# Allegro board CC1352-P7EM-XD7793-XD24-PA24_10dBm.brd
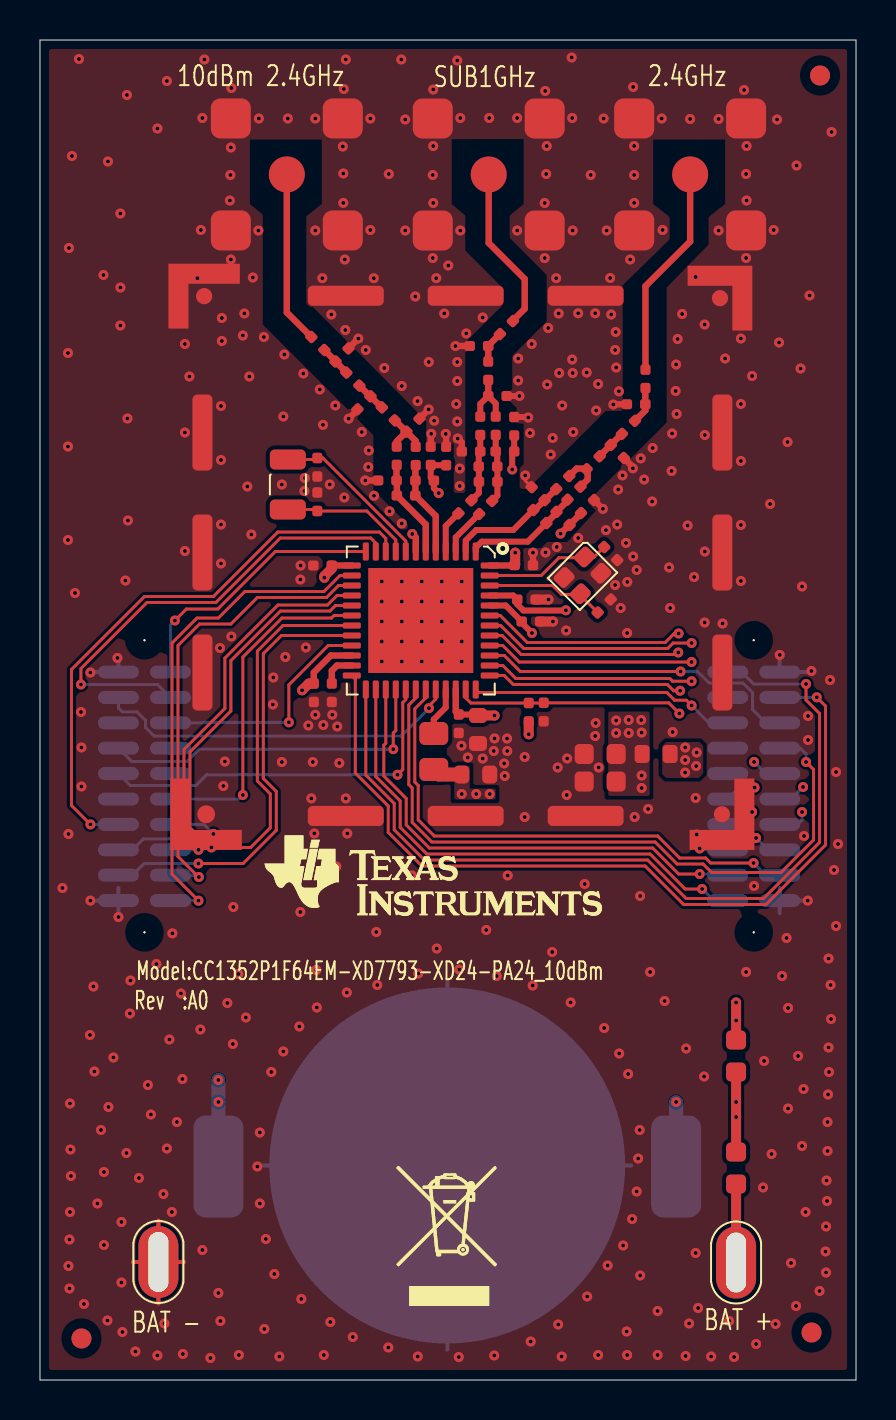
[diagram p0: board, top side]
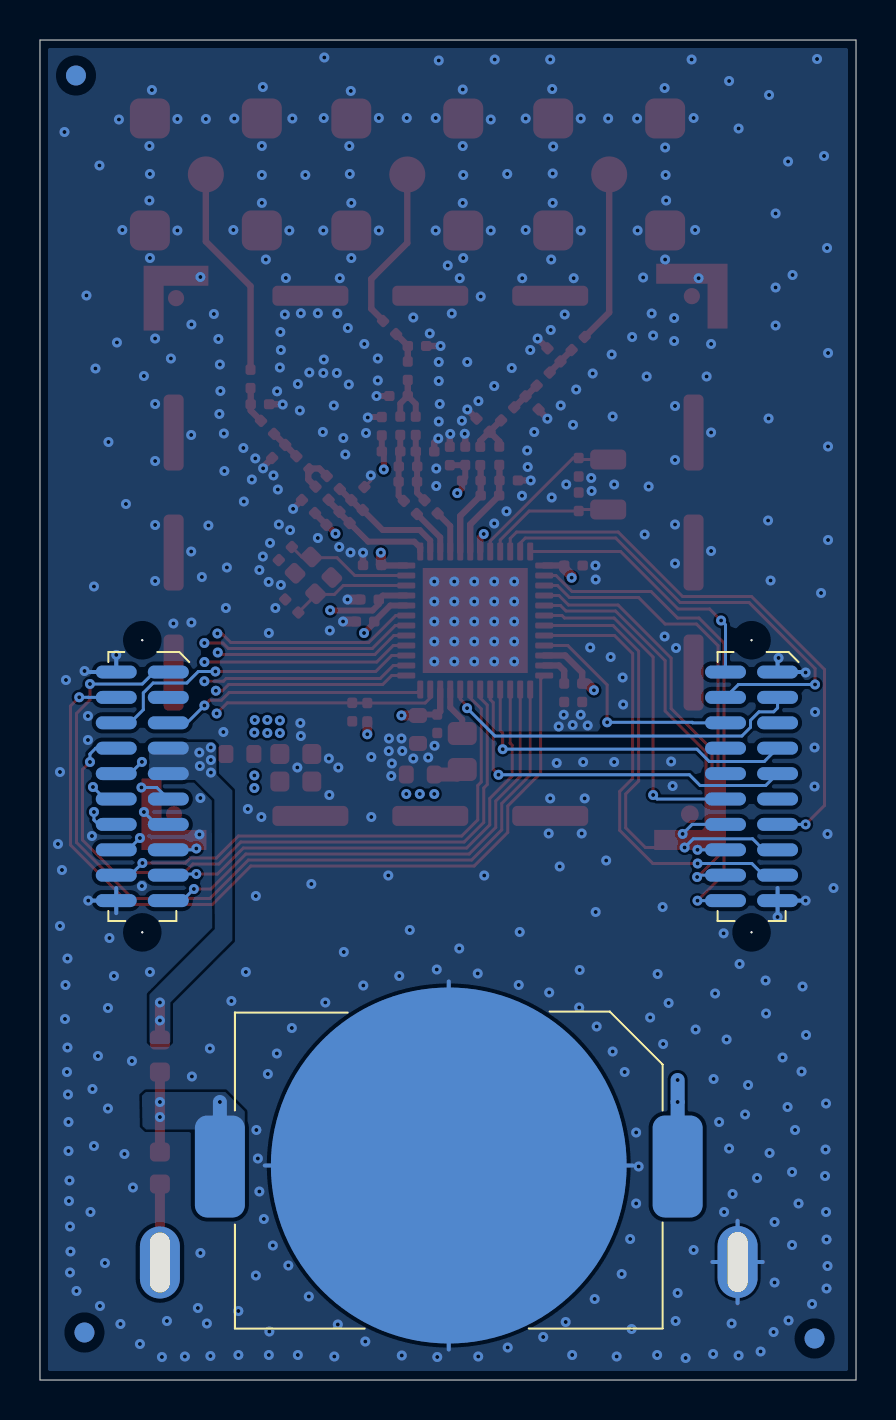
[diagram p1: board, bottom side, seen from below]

Outline 40.83 x 67 mm; copper layers: TOP, L2, L3, BOTTOM. Coordinates in mm from the lower left corner of the outline.
Outline path: 0,67 0,0 40.83,0 40.83,67 0,67

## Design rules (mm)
constraint set DEFAULT: min track width 0.15

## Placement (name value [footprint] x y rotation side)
BAT+1  BAT+  [PAD_S2000OBL3600_1000M3000]  34.83 5.88 0 top
BAT-1  BAT-  [PAD_S2000OBL3600_1000M3000]  5.92 5.9 0 top
BT1  BAT-HLD-001  [BAT_BATHLD001N]  8.92 10.68 0 bottom
C1  22uF  [CAPC1608X100A2N#2]  28.83 29.93 180 top
C2  22uF  [CAPC1608X100A2N#2]  28.83 31.3 180 top
C11  12pF  [CAPC1005X60B2N]  27.06 43.35 45 top
C12  1.1pF  [CAPC1005X60B2N]  26.39 44.01 45 top
C13  1pF  [CAPC1005X60B2N]  28.56 46.75 315 top
C14  1pF  [CAPC1005X60B2N]  30.28 48.79 180 top
C15  12pF  [CAPC1005X60B2N]  30.29 49.59 90 top
C21  1.1pF  [CAPC1005X60B2N]  25.25 43.99 135 top
C31  1.2pF  [CAPC1005X60B2N]  22.88 44.92 180 top
C32  100pF  [CAPC1005X60B2N]  23.73 47.23 90 top
C33  3pF  [CAPC1005X60B2N]  22.8 47.25 90 top
C34  2.7pF  [CAPC1005X60B2N]  22.42 49.2 0 top
C35  5.6pF  [CAPC1005X60B2N]  21.5 51.7 0 top
C36  100pF  [CAPC1005X60B2N]  23.66 52.95 225 top
C41  3pF  [CAPC1005X60B2N]  21.1 46.43 0 top
C51  12pF  [CAPC1005X60B2N]  19.55 46.67 270 top
C52  10nF  [CAPC1005X60B2N]  20.32 45.74 90 top
C53  1.2pF  [CAPC1005X60B2N]  18.8 45.74 90 top
C54  1.2pF  [CAPC1005X60B2N]  18.33 47.42 45 top
C55  1.4pF  [CAPC1005X60B2N]  16.53 49.18 225 top
C56  1.6pF  [CAPC1005X60B2N]  14.78 50.93 45 top
C57  6.8pF  [CAPC1005X60B2N]  14.23 51.5 135 top
C61  1.2pF  [CAPC1005X60B2N]  16.91 44.98 0 top
C81  12pF  [CAPC1005X60B2N]  13.88 46.1 270 top
C91  12pF  [CAPC1005X60B2N]  13.88 43.45 90 top
C131  0.1uF  [CAPC1005X60B2N]  14.6 40.73 180 top
C221  0.1uF  [CAPC1005X60B2N]  13.7 34.83 270 top
C231  1uF  [CAPC1005X60B2N]  14.6 34.83 270 top
C331  22uF  [CAPC1608X100A2N]  21.1 30.28 0 top
C341  22uF  [CAPC1608X100A2N]  21.91 33.23 270 top
C342  0.1uF  [CAPC1005X60B2N]  20.95 33.28 270 top
C351  0.1uF  [CAPC1005X60B2N]  25.2 33.86 270 top
C441  0.1uF  [CAPC1005X60B2N]  24.1 37.93 0 top
C451  0.1uF  [CAPC1005X60B2N]  23.87 39.03 0 top
C461  7.5pF  [CAPC1005X60B2N]  27.9 38.38 45 top
C471  7.5pF  [CAPC1005X60B2N]  28.23 41.65 315 top
C481  0.1uF  [CAPC1005X60B2N]  23.74 40.74 0 top
FIDU1  FIDU_1MM  [FID100X115B]  2.08 2.08 0 top
FIDU2  FIDU_1MM  [FID100X115B]  38.6 2.38 0 top
FIDU3  FIDU_1MM  [FID100X115B]  39.02 65.22 0 top
FIDU4  FIDU_1MM  [FID100X115B]  2.08 2.08 180 bottom
FIDU5  FIDU_1MM  [FID100X115B]  38.6 2.38 180 bottom
FIDU6  FIDU_1MM  [FID100X115B]  39.02 65.22 180 bottom
FL1  BLM18HE152SN1  [FIL_BLM18HE152SN1DN]  30.12 31.3 0 top
J1  SMA-10V21-TGG  [HUSTSAN_SMA10V21TGGAN]  22.45 60.28 0 top
J2  SMA-10V21-TGG  [HUSTSAN_SMA10V21TGGAN]  32.53 60.28 0 top
J3  SMA-10V21-TGG  [HUSTSAN_SMA10V21TGGAN]  12.35 60.28 0 top
L11  15nH  [INDC1005X60D2N]  25.33 42.85 135 top
L12  2.4nH  [INDC1005X60D2N]  26.49 42.76 135 top
L13  1.5nH  [INDC1005X60D2N]  27.35 45.54 45 top
L14  2nH  [INDC1005X60D2N]  29.11 47.31 45 top
L21  2.4nH  [INDC1005X60D2N]  25.83 44.55 45 top
L31  3.9nH  [INDC1005X60D2N]  21.97 43.3 45 top
L32  22nH  [INDC1005X60D2N]  22.87 45.68 180 top
L33  10nH  [INDC1005X60D2N]  23.72 46.43 180 top
L34  7.5nH  [INDC1005X60D2N]  22.42 50 90 top
L41  3.9nH  [INDC1005X60D2N]  20.93 43.33 45 top
L42  10nH  [INDC1005X60D2N]  22.03 47.25 90 top
L51  15nH  [INDC1005X60D2N]  18.78 44.22 180 top
L52  2nH  [INDC1005X60D2N]  19.71 44.97 180 top
L53  1.6nH  [INDC1005X60D2N]  17.75 47.98 135 top
L54  1nH  [INDC1005X60D2N]  15.98 49.72 135 top
L61  2nH  [INDC1005X60D2N]  17.85 45.75 90 top
L331  6.8uH  [INDC2012X150A2N]  19.7 32.33 270 top
LBL1  TI_LOGO  [TI_LOGO_1]  12.23 27.23 0 top
LBL6  TRASH_7mm  [TRASH_7MM]  18.47 3.7 0 top
NOREF  -  []  -63.85 -68.35 0 top
NOREF#2  -  []  0 54.83 0 top
NOREF#3  -  []  38.27 0 90 top
P1  SFM-110-02-S-D-A-K  [SAMTEC_SFM11002AN]  3.92 35.4 0 bottom
P2  SFM-110-02-S-D-A-K  [SAMTEC_SFM11002AN]  34.4 35.4 0 bottom
R1  0  [RESC1608X55A2N]  34.83 9.8 90 top
R2  0  [RESC1608X55A2N]  34.83 15.4 90 top
R351  100k  [RESC1005X40B2N]  24.45 33.85 270 top
SC1  BMIS-203  [MECH_BMIS203_A2N]  8.41 28.19 0 top
U1  CC1352P1F64TRGZ  [QFNFC50P700X700X100-49A2N]  21.8 41.43 180 top
Y1  32.768kHz  [XTAL_TZ1166C_B2N]  12.4 46.03 270 top
Y2  48MHz  [OSCCC200X160X50-4A2N]  27.25 41.15 225 top

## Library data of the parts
BAT+1 = BAT+
BAT-1 = BAT-
BT1 = BATT_3PINS: User Part Number: #PN; alternate symbols: (BAT_BATHLD001L,BAT_BATHLD001M,BAT_BATHLD001AL,BAT_BATHLD001AM)
C1 C2 C331 C341 = CAPACITOR: User Part Number: #PN; alternate symbols: (CAPC1608X100A2L,CAPC1608X100A2M)
C11-C15 C21 C31-C36 C41 C51-C57 C61 C81 C91 C131 C221 C231 C342 C351 C441 C451 C461 C471 C481 = CAPACITOR: User Part Number: #PN
FIDU1-FIDU6 = FIDMARK
FL1 = FILTER_2PIN: alternate symbols: (FIL_BLM18HE152SN1DL,FIL_BLM18HE152SN1DM)
J1-J3 = CONN_COAX_1+4: alternate symbols: (HUSTSAN_SMA10V21TGGL,HUSTSAN_SMA10V21TGGM)
L11 L31 L33 L41 L42 L51 = INDUCTOR_HOR_1_2: User Part Number: #PN; alternate symbols: (INDC1005X60C2L,INDC1005X60C2M)
L12-L14 L21 L32 L34 L52-L54 L61 = INDUCTOR_HOR_1_2: User Part Number: #PN
L331 = INDUCTOR: User Part Number: #PN; alternate symbols: (INDC2012X150A2L,INDC2012X150A2M)
LBL1 = TI_LOGO_V1
LBL6 = TRASH_V2: User Part Number: #PN
P1 P2 = CONN_HEADER_2X10_P_S: alternate symbols: (SAMTEC_SFM11002AL,SAMTEC_SFM11002AM)
R1 R2 = RESISTOR: User Part Number: #PN; alternate symbols: (RESC1608X55A2L,RESC1608X55A2M)
R351 = RESISTOR: User Part Number: #PN
SC1 = SHIELD_COVER_BMIS-203
U1 = IC_RF_CC1352P1F64_QFN48: User Part Number: #PN; alternate symbols: (QFNFC50P700X700X100-49A2L,QFNFC50P700X700X100-49A2M)
Y1 = XTAL: User Part Number: #PN; alternate symbols: (XTAL_TZ1166C_B2L,XTAL_TZ1166C_B2M)
Y2 = XTAL_4_V3: User Part Number: #PN; alternate symbols: (OSCCC200X160X50-4A2L,OSCCC200X160X50-4A2M)

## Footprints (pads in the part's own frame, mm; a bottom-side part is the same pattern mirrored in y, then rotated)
BAT_BATHLD001N
  custom 0.625x0.625 smd: 1(0,0) 2(22.9,0)
  round 17.8 smd: 3(11.45,-0.05)
CAPC1005X60B2N
  custom 0.125x0.125 smd: 1(0,0) 2(0.924,0)
CAPC1608X100A2N
  custom 0.188x0.188 smd: 1(0,0) 2(1.4,0)
CAPC1608X100A2N#2
  custom 0.237x0.237 smd: 1(0,0) 2(1.6,0)
FID100X115B
  round 1 smd: 1(0,0)
FIL_BLM18HE152SN1DN
  custom 0.188x0.188 smd: 1(0,0) 2(1.4,0)
HUSTSAN_SMA10V21TGGAN
  round 1.801 smd: 1(0,0)
  custom 0.5x0.5 smd: 2(-2.8,-2.8) 3(2.8,-2.8) 4(2.8,2.8) 5(-2.8,2.8)
INDC1005X60D2N
  custom 0.125x0.125 smd: 1(0,0) 2(0.924,0)
INDC2012X150A2N
  custom 0.287x0.287 smd: 1(0,0) 2(1.8,0)
MECH_BMIS203_A2N
  custom 0.892x0.892 smd: 1(-0.1,0.1)
  custom 0.25x0.25 smd: 2(6.885,0.015) 3(12.885,0.015) 4(18.885,0.015) 6(25.725,7.185) 7(25.725,13.185) 8(25.725,19.185) 10(18.885,26.025) 11(12.885,26.025) 12(6.885,26.025) 14(-0.285,19.185) 15(-0.285,13.185) 16(-0.285,7.185)
  custom 0.81x0.81 smd: 5(25.705,0.1) 9(25.605,25.905) 13(-0.2,26.005)
OSCCC200X160X50-4A2N
  custom 0.2x0.2 smd: 1(0,0) 2(1.45,0) 3(1.45,1.15) 4(0,1.15)
PAD_S2000OBL3600_1000M3000
  oval 2x3.6 hole 1x3: 1(0,0)
QFNFC50P700X700X100-49A2N
  custom 0.075x0.075 smd: 1(0,0) 2(0.5,0) 3(1,0) 4(1.5,0) 5(2,0) 6(2.5,0) 7(3,0) 8(3.5,0) 9(4,0) 10(4.5,0) 11(5,0) 12(5.5,0) 13(6.2,0.7) 14(6.2,1.2) 15(6.2,1.7) 16(6.2,2.2) 17(6.2,2.7) 18(6.2,3.2) 19(6.2,3.7) 20(6.2,4.2) 21(6.2,4.7) 22(6.2,5.2) 23(6.2,5.7) 24(6.2,6.2) 25(5.5,6.9) 26(5,6.9) 27(4.5,6.9) 28(4,6.9) 29(3.5,6.9) 30(3,6.9) 31(2.5,6.9) 32(2,6.9) 33(1.5,6.9) 34(1,6.9) 35(0.5,6.9) 36(0,6.9) 37(-0.7,6.2) 38(-0.7,5.7) 39(-0.7,5.2) 40(-0.7,4.7) 41(-0.7,4.2) 42(-0.7,3.7) 43(-0.7,3.2) 44(-0.7,2.7) 45(-0.7,2.2) 46(-0.7,1.7) 47(-0.7,1.2) 48(-0.7,0.7)
  rect 5.25x5.25 smd: 49(2.75,3.45)
RESC1005X40B2N
  custom 0.125x0.125 smd: 1(0,0) 2(0.924,0)
RESC1608X55A2N
  custom 0.237x0.237 smd: 1(0,0) 2(1.6,0)
SAMTEC_SFM11002AN
  round 0.099 hole 1.501 unplated: (1.302,-1.588) (1.302,13.017)
  oval 2.05x0.65 smd: 1(0,0) 2(2.604,0) 3(0,1.27) 4(2.604,1.27) 5(0,2.54) 6(2.604,2.54) 7(0,3.81) 8(2.604,3.81) 9(0,5.08) 10(2.604,5.08) 11(0,6.35) 12(2.604,6.35) 13(0,7.62) 14(2.604,7.62) 15(0,8.89) 16(2.604,8.89) 17(0,10.16) 18(2.604,10.16) 19(0,11.43) 20(2.604,11.43)
XTAL_TZ1166C_B2N
  custom 0.25x0.25 smd: 1(0,0) 2(2.5,0)

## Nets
GND: BAT-1.1 BT1.3(-) C1.2 C2.2 C11.2 C13.2 C14.2 C21.2 C32.2 C34.2 C35.1 C41.1 C51.1 C52.2 C54.2 C55.2 C56.2 C61.1 C81.2 C91.2 C131.2 C221.2 C231.2 C331.2 C341.2 C342.2 C351.2 C441.2 C451.2 C461.2 C471.2 C481.2 J1.2 J1.3 J1.4 J1.5 J2.2 J2.3 J2.4 J2.5 J3.2 J3.3 J3.4 J3.5 P1.1 P1.19 P2.2 P2.20 SC1.1 SC1.2 SC1.3 SC1.4 SC1.5 SC1.6 SC1.7 SC1.8 SC1.9(GND#9) SC1.10 SC1.11 SC1.12 SC1.13 SC1.14 SC1.15 SC1.16 U1.49 Y2.2 Y2.4(GND#4)
VDD_EB: FL1.2 P2.7 P2.9 R2.2
VDDR: C51.2 C52.1 C331.1 C451.1 C481.1 L52.1 L331.2 U1.45 U1.48
VDDS: C1.1 C2.1 C131.1 C221.1 C341.1 C342.1 C441.1 FL1.1 R351.2 U1.13 U1.22 U1.34 U1.44
DCDC_SW: L331.1 U1.33
DIO_5: P1.13 U1.10
DIO_6: P1.4 U1.11
DIO_7: P1.2 U1.12
DIO_8: P1.20 U1.14
DIO_9: P1.18 U1.15(DIO_9)
DIO_10: P1.16 U1.16
DIO_11: P1.14 U1.17
DIO_12: P1.12 U1.18
DIO_13: P1.15 U1.19
DIO_14: P1.17 U1.20
DIO_15: P1.6 U1.21
DIO_16 / JTAG TDO: P2.19 U1.26
DIO_17 / JTAG TDI: P2.17 U1.27
DIO_18: P1.7 U1.28
DIO_19: P1.9 U1.29
DIO_20: P2.8 U1.30
DIO_21: P2.18 U1.31
DIO_22: P1.3 U1.32
DIO_23: P2.5 U1.36
DIO_24: P2.10 U1.37
DIO_25: P2.11 U1.38
DIO_26: P2.6 U1.39
DIO_27: P2.13 U1.40
DIO_28: P2.16 U1.41
DIO_29: P2.14 U1.42
DIO_30: P2.12 U1.43
JTAG_TCK: P2.1 U1.25
JTAG_TMS: P2.4 U1.24
NRESET: C351.1 P2.15 R351.1 U1.35
RX_TX: C11.1 C32.1 L12.1 L33.1 U1.7
N485531: C36.1 J1.1
N485663: C33.2 C34.1 L34.1 L42.2
N485675: C35.2 C36.2 L34.2
N485699: C231.1 U1.23
N485705: C81.1 U1.8 Y1.1
N485903: C31.1 C33.1 L31.2 L32.1 L33.2
N501936: C471.1 U1.47 Y2.1
N501950: C461.1 U1.46 Y2.3
N510840: C12.1 L11.1 L12.2 U1.1
N510850: C21.1 L11.2 L21.1 U1.2
N512042: C13.1 L13.2 L14.1
N512564: C15.2 J2.1
N514814: C12.2 L13.1 L21.2
N516767: C31.2 C41.2 L32.2 L41.2 L42.1
N517777: C61.2 L51.2 L61.1 U1.6
N517785: C53.1 L51.1 L52.2 U1.5
N517815: C53.2 C54.1 L53.1 L61.2
N517942: C55.1 L53.2 L54.1
N518069: C56.1 C57.1 L54.2
N520038: C57.2 J3.1
N520167: L41.1 U1.4
N553230: C14.1 C15.1 L14.2
N613500: L31.1 U1.3
N621290: C91.1 U1.9 Y1.2
N2095591: BAT+1.1 R1.1
N2095595: BT1.1 BT1.2 R1.2 R2.1

Pads without a net: FIDU1 1; FIDU2 1; FIDU3 1; FIDU4 1; FIDU5 1; FIDU6 1; P1 5 8 10 11; P2 3

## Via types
v1: diameter 0.5, hole 0.2, TOP to BOTTOM, 542 vias

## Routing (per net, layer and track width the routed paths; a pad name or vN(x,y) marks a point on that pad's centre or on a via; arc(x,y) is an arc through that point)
GND: length 83.8
  TOP w0.15: C21.2 24.27,44.97 v1(24.27,45.23)
  TOP w0.203: 4.65,5.9 BAT-1.1 ; BAT-1.1 5.92,3.82 ; BAT-1.1 7.2,5.9 ; BAT-1.1 5.92,7.98
  TOP w0.3: 23.73,48.15 24.4,48.15 v1(24.43,48.12) ; 27.72,44 v1(28.16,43.56) ; v1(23.99,49.2) C34.2
  TOP w0.32: 18.98,48.07 v1(19.44,48.53) ; v1(20.9,47.08) 21.1,46.88 C41.1 ; v1(19.58,47.31) 19.55,47.28 C51.1 ; v1(20.3,47.3) 20.32,47.28 C52.2 ; v1(29.66,45.58) 29.66,45.65 C13.2 ; v1(16.27,44.98) C61.1 ; v1(20.79,51.7) C35.1 ; v1(15.44,48.07) 15.88,48.51 15.88,48.53 ; v1(28.68,48.78) 28.7,48.79 C14.2 ; C481.2 v1(24.66,41.37) ; v1(15.93,52.07) 15.44,51.58
  TOP w0.5: C441.2 v1(25.66,37.93) ; C451.2 v1(25.44,39.03)
  L2 w0.203: BAT-1.1 5.92,7.95 ; BAT-1.1 7.18,5.9 ; BAT-1.1 4.67,5.9 ; BAT-1.1 5.92,3.85
  L3 w0.203: 5.92,3.85 BAT-1.1 ; BAT-1.1 5.92,7.95 ; BAT-1.1 4.67,5.9 ; BAT-1.1 7.18,5.9
  BOTTOM w0.203: BAT-1.1 5.92,7.95 ; BAT-1.1 4.67,5.9 ; BAT-1.1 7.18,5.9 ; BAT-1.1 5.92,3.85 ; 11.17,10.73 BT1.3 ; BT1.3 20.38,19.93 ; BT1.3 20.38,1.52 ; BT1.3 29.58,10.73 ; P1.19 3.92,24.6 ; P1.19 2.6,23.97 ; P1.19 3.92,23.34 ; 2.6,35.4 P1.1 3.92,36.03 ; 37.01,23.34 P2.20 ; P2.20 37.01,24.6 ; P2.20 38.34,23.97 ; 37.01,36.03 P2.2 38.34,35.4
  vias: v1(1.12,24.6) v1(1.45,56.6) v1(1.4,51.35) v1(1.4,46.68) v1(1.4,42) v1(1.42,27.3) v1(1.47,7.03) v1(1.42,5.7) v1(1.47,4.58) v1(1.5,13.83) v1(1.52,11.53) v1(1.55,10.2) v1(1.5,8.4) v1(1.6,61.2) v1(1.75,39.35) v1(1.95,66.05) v1(2.05,33.4) v1(2.08,31.62) v1(2.08,29.68) v1(2.2,3.8) v1(2.52,35.38) v1(2.52,23.97) v1(2.5,17.25) v1(2.67,19.68) v1(2.72,15.43) v1(2.88,8.83) v1(3.05,12.5) v1(3.17,55.25) v1(3.2,10.4) v1(3.2,6.75) v1(3.4,60.93) v1(3.42,13.65) v1(3.38,2.98) v1(3.67,16.12) v1(3.88,36.1) v1(3.92,23.15) v1(4.02,58.33) v1(4.02,54.62) v1(4.02,52.73) v1(4.08,7.9) v1(4.08,4.88) v1(4.12,2.4) v1(4.27,39.98) v1(4.35,64.25) v1(4.33,11.35) v1(4.38,48.08) v1(4.4,42.98) v1(4.52,19.98) v1(4.5,18.33) v1(4.77,1.43) v1(4.95,10.1) v1(5.4,14.75) v1(5.55,13.28) v1(5.83,20.8) v1(5.88,62.58) v1(5.88,1.23) v1(6.17,9.3) v1(6.22,2.83) v1(6.35,64.95) v1(6.35,11.58) v1(6.47,17.03) v1(6.62,22.33) v1(6.6,8.4) v1(6.85,12.9) v1(7.05,19.33) v1(7.12,15.05) v1(7.15,1.3) v1(7.25,51.8) v1(7.25,47.38) v1(7.25,41.45) v1(7.47,50.18) v1(7.88,55.09) v1(8.05,57.5) v1(8.02,17.53) v1(8.12,63.1) v1(8.12,6.5) v1(8.22,66.03) v1(8.52,1.1) v1(8.92,4.35) v1(9.05,48.7) v1(9.05,46) v1(9.05,42.78) v1(9.05,40.83) v1(9,36.6) v1(9.02,2.95) v1(9.1,53.1) v1(9.1,51.95) v1(9.17,29.7) v1(9.25,30.93) v1(9.38,18.85) v1(9.55,61.62) v1(9.52,60.25) v1(9.5,58.97) v1(9.55,56.03) v1(9.58,64.6) v1(9.58,37.18) v1(9.65,16.8) v1(9.67,23.65) v1(9.92,20.3) v1(9.95,1.25) v1(10.15,52.23) v1(10.22,53.33) v1(10.3,18.12) v1(10.47,50.18) v1(10.38,44.68) v1(10.65,55.12) v1(10.58,42.28) v1(10.95,63.08) v1(10.93,57.47) v1(10.88,10.68) v1(11,12.38) v1(11,8.83) v1(11.2,52.15) v1(11.22,2.55) v1(11.3,7.05) v1(11.65,33.78) v1(11.58,15.4) v1(11.67,35.12) v1(11.72,5.3) v1(11.97,1.18) v1(12.17,48.18) v1(12.1,44.78) v1(12.1,30.9) v1(12.17,16.43) v1(12.22,51.28) v1(12.27,36.15) v1(12.4,63.08) v1(12.5,25.98) v1(12.97,17.68) v1(13.04,40.73) v1(13.02,40.03) v1(13.02,23.4) v1(13.17,50.33) v1(13.08,4.05) v1(13.25,45.1) v1(13.23,44.45) v1(13.3,36.62) v1(13.42,32.73) v1(13.65,30.9) v1(13.58,29.08) v1(13.77,63.08) v1(13.77,57.47) v1(13.77,33.26) v1(13.72,27.33) v1(13.83,20.5) v1(13.85,18.62) v1(14,49.53) v1(14.12,55.09) v1(14.16,47.76) v1(14.17,32.75) v1(14.2,1.25) v1(14.5,44.78) v1(14.52,2.9) v1(14.58,53.28) v1(14.62,33.26) v1(14.77,48.73) v1(14.83,25.68) v1(14.88,32.68) v1(14.97,30.85) v1(15.15,61.68) v1(15.17,60.33) v1(15.17,58.86) v1(15.2,64.55) v1(15.25,56.03) v1(15.27,52.5) v1(15.22,44.12) v1(15.3,66.03) v1(15.3,29.08) v1(15.35,19.38) v1(15.38,27.33) v1(15.65,2.15) v1(16.1,47.4) v1(16.3,51.5) v1(16.45,46.48) v1(16.42,45.65) v1(16.53,63.08) v1(16.53,57.5) v1(16.7,55.09) v1(16.71,44.21) v1(16.83,22.4) v1(16.88,19.75) v1(17.1,39.93) v1(17.1,38.93) v1(17.1,37.93) v1(17.1,36.93) v1(17.1,35.93) v1(17.22,50.6) v1(17.45,60.3) v1(17.42,1.62) v1(17.49,43.44) v1(18.08,66.03) v1(18.1,49.7) v1(18.1,42.83) v1(18.1,39.93) v1(18.1,38.93) v1(18.1,37.93) v1(18.1,36.93) v1(18.1,35.93) v1(18.27,63.03) v1(18.27,57.47) v1(18.6,25.23) v1(18.77,54.18) v1(18.89,48.95) v1(18.92,20.33) v1(18.9,1.18) v1(19.1,39.93) v1(19.1,38.93) v1(19.1,37.93) v1(19.1,36.93) v1(19.1,35.93) v1(19.45,50.9) v1(19.65,60.25) v1(19.65,56.1) v1(19.67,64.53) v1(19.67,61.7) v1(19.67,58.85) v1(19.72,47.96) v1(19.83,55.09) v1(19.85,21.58) v1(20.1,39.93) v1(20.1,38.93) v1(20.1,37.93) v1(20.1,36.93) v1(20.1,35.93) v1(20.22,53.33) v1(20.42,55.72) v1(20.83,48.8) v1(20.88,65.97) v1(20.88,50.9) v1(20.88,49.95) v1(20.88,47.93) v1(20.97,20.53) v1(20.95,1.15) v1(21.03,63.1) v1(21.03,57.47) v1(21,45.58) v1(21,44.7) v1(21.1,39.93) v1(21.1,38.93) v1(21.1,37.93) v1(21.1,36.93) v1(21.1,35.93) v1(21.09,31.71) v1(21.33,52.33) v1(21.4,31.12) v1(22.15,53.12) v1(22.15,31.07) v1(22.33,22.5) v1(22.48,63.1) v1(22.74,32.08) v1(22.7,31.45) v1(22.73,1.23) v1(22.85,20.2) v1(23.22,30.83) v1(23.25,30.2) v1(23.37,32.07) v1(23.38,31.45) v1(23.4,25.23) v1(23.87,63.1) v1(23.87,57.47) v1(23.92,51.08) v1(23.92,49.98) v1(24.25,31.15) v1(24.25,28.15) v1(24.52,47.35) v1(24.55,1.93) v1(24.6,51.8) v1(24.65,19.73) v1(25.27,64.45) v1(25.25,58.85) v1(25.25,56.1) v1(25.35,61.7) v1(25.33,60.3) v1(25.37,49.78) v1(25.29,41.38) v1(25.42,52.6) v1(25.55,46.28) v1(25.65,47.1) v1(25.62,21.4) v1(25.83,55.09) v1(25.86,41.65) v1(25.95,53.33) v1(25.9,30.62) v1(25.92,2.78) v1(25.98,50.35) v1(26.12,48.73) v1(26.1,1.18) v1(26.33,37.48) v1(26.37,31.08) v1(26.35,29.25) v1(26.55,18.88) v1(26.6,66.12) v1(26.63,63.1) v1(26.65,57.47) v1(26.62,51.03) v1(26.65,50.35) v1(26.67,47.4) v1(26.92,53.34) v1(26.92,42.1) v1(27.25,24.8) v1(27.35,50.38) v1(27.37,4.18) v1(27.55,60.25) v1(27.77,53.34) v1(27.77,32.2) v1(27.83,48.48) v1(27.8,32.85) v1(27.92,49.8) v1(27.95,30.62) v1(27.92,1.25) v1(28.2,63.08) v1(28.23,17.6) v1(28.35,57.47) v1(28.31,42.49) v1(28.4,5.73) v1(28.52,55.1) v1(28.58,53.28) v1(28.77,51.5) v1(28.77,39.75) v1(28.8,52.4) v1(28.83,50.62) v1(28.87,42.78) v1(28.96,49.44) v1(28.92,44.53) v1(29.05,38.6) v1(28.98,16.33) v1(29.14,45.23) v1(29.17,6.73) v1(29.32,41.85) v1(29.37,37.35) v1(29.35,2.43) v1(29.37,1.25) v1(29.38,39.9) v1(29.42,15.3) v1(29.52,56.03) v1(29.62,8.05) v1(29.67,64.65) v1(29.73,61.7) v1(29.73,60.25) v1(29.73,58.86) v1(29.67,41.18) v1(29.75,28.15) v1(29.85,40.5) v1(29.85,9.43) v1(29.92,11.08) v1(30.05,46.08) v1(30.02,24.2) v1(30,12.5) v1(30.02,5.23) v1(30.23,45.03) v1(30.42,28.55) v1(30.52,20.4) v1(30.65,46.6) v1(30.62,43.93) v1(30.9,3.45) v1(30.9,1.25) v1(31.1,63.08) v1(31.15,57.5) v1(31.25,18.95) v1(31.48,40.62) v1(31.52,38.6) v1(31.62,47.33) v1(31.6,45.45) v1(31.65,32.4) v1(31.83,50.78) v1(31.8,49.45) v1(31.85,48.3) v1(31.9,52.05) v1(32.12,53.3) v1(32.33,16.58) v1(32.3,1.2) v1(32.4,42.73) v1(32.52,63.05) v1(32.48,2.83) v1(32.73,40.15) v1(32.8,55.15) v1(32.8,29.1) v1(32.85,27.28) v1(32.8,6.35) v1(32.92,3.6) v1(33.25,52.78) v1(33.26,47.25) v1(33.26,41.43) v1(33.25,37.88) v1(33.23,15.18) v1(33.58,1.18) v1(33.95,63.05) v1(33.95,57.47) v1(34.15,37.83) v1(34.27,51.08) v1(34.48,2.95) v1(34.73,1.15) v1(35.06,52.08) v1(35.06,48.8) v1(35.06,45.95) v1(35.06,42.75) v1(35.06,39.95) v1(35.23,64.5) v1(35.35,61.7) v1(35.33,60.3) v1(35.35,58.97) v1(35.33,56.1) v1(35.33,20.4) v1(35.62,50.2) v1(35.73,24.7) v1(35.83,1.8) v1(36.17,9.62) v1(36.23,15.95) v1(36.52,43.8) v1(36.6,11.3) v1(36.7,57.5) v1(36.87,63.03) v1(36.8,2.8) v1(36.98,51.88) v1(37.01,36.25) v1(37.12,20.2) v1(37.35,22.1) v1(37.4,46.9) v1(37.42,18.6) v1(37.42,13.58) v1(37.58,5.85) v1(37.85,60.72) v1(37.83,3.7) v1(37.92,16.2) v1(38.05,50.58) v1(38.12,39.68) v1(38.12,11.7) v1(38.23,27.2) v1(38.2,14.55) v1(38.3,8.4) v1(38.42,33.2) v1(38.42,32) v1(38.41,23.97) v1(38.5,54.22) v1(38.59,35.45) v1(39,4.45) v1(39.35,9.98) v1(39.37,8.95) v1(39.33,7.68) v1(39.3,6.43) v1(39.33,5.38) v1(39.45,21.08) v1(39.45,16.62) v1(39.42,14.28) v1(39.4,12.9) v1(39.4,11.45) v1(39.52,35) v1(39.55,19.75) v1(39.48,15.4) v1(39.6,62.4) v1(39.58,18.05) v1(39.73,25.5) v1(39.83,30.4) v1(39.83,22.7) v1(39.92,26.8)
VDD_EB: length 1.9
  TOP w0.5: v1(34.83,18.88) v1(34.83,17.98) R2.2
  vias: v1(32.27,30.37) v1(32.28,31.63) v1(32.28,31) v1(32.85,31.37) v1(32.83,30.7)
VDDR: length 10
  TOP w0.3: C52.1 19.56,45.74 C51.2 19.55,45.13 L52.1 19.71,44.59 v1(19.95,44.34) ; U1.45 23.67,39.23 C451.1 23.87,38.79 24.19,38.48 26.3,38.48 v1(26.31,38.48)
  TOP w0.32: C481.1 23.73,40.73 U1.48
  TOP w0.5: v1(23.77,41.37) 23.77,40.78 C481.1
  TOP w0.7: C331.1 19.95,30.28 L331.2
  vias: v1(21.1,29.3) v1(21.83,29.3) v1(22.5,29.3)
VDDS: length 11.8
  TOP w0.3: C341.1 21.86,33.28 C342.1 ; U1.44 23.3,38.73 C441.1 24.1,37.86 v1(24.61,37.35)
  TOP w0.32: C131.1 U1.13 ; U1.34 20.8,33.43 C342.1 ; U1.22 14.55,36.23 13.7,35.38 C221.1
  TOP w0.5: C221.1 13.45,34.83 v1(13.11,34.49) ; R351.2 v1(24.45,32.29) ; C341.1 v1(22.74,33.23) ; v1(14.23,40.11) 14.23,40.2 14.6,40.57 C131.1
  vias: v1(28.83,32.98) v1(28.83,32.35) v1(29.45,33) v1(29.45,32.35) v1(30.08,33) v1(30.1,32.37) v1(30.1,30.23) v1(30.1,29.6)
DCDC_SW: length 2.4
  TOP w0.3: U1.33 20.3,33.62 19.7,33.03 L331.1
DIO_5: length 28.9
  TOP w0.15: U1.10 17.3,42.08 16.98,42.4 11.9,42.4 8.67,39.18 5.23,39.18 1.58,35.52 1.58,28.73 v1(2.52,27.78)
  BOTTOM w0.15: P1.13 v1(2.52,27.78)
DIO_6: length 23.5
  TOP w0.15: U1.11 16.8,41.84 16.54,42.1 12.02,42.1 8.8,38.88 5.35,38.88 2.05,35.57 v1(2.05,34.78)
  BOTTOM w0.15: P1.4 5.88,34.78 v1(2.05,34.78)
DIO_7: length 13.6
  TOP w0.15: U1.12 11.77,41.43 8.9,38.55 7.33,38.55 v1(6.75,37.98)
  BOTTOM w0.15: v1(6.75,37.98) 6.53,37.75 P1.2
DIO_8: length 25.2
  TOP w0.15: v1(7.93,23.97) 6.6,25.29 6.6,36.84 7.86,38.1 8.92,38.1 10.25,39.43 14.21,39.43 15.01,40.23 U1.14
  BOTTOM w0.15: v1(7.93,23.97) 7.78,23.97 7.78,23.97 P1.20
DIO_9: length 23.4
  TOP w0.15: v1(7.95,25.15) 7.93,25.15 6.9,26.18 6.9,36.72 7.98,37.8 9.55,37.8 10.88,39.12 14.33,39.12 14.94,39.73 U1.15
  BOTTOM w0.15: v1(7.95,25.15) 7.86,25.24 P1.18
DIO_10: length 19.8
  TOP w0.15: v1(7.93,26.51) 7.2,27.24 7.2,31.53 9.25,33.58 9.25,36.09 11.91,38.75 14.38,38.75 14.86,39.23 U1.16
  BOTTOM w0.15: v1(7.93,26.51) P1.16
DIO_11: length 20
  TOP w0.15: U1.17 14.78,38.73 14.51,38.45 12.03,38.45 9.55,35.97 9.55,33.45 7.5,31.4 7.5,27.61 7.81,27.3 v1(8.67,27.3)
  BOTTOM w0.15: P1.14 8.2,27.78 v1(8.67,27.3)
DIO_12: length 16.9
  TOP w0.15: U1.18 14.71,38.23 14.58,38.1 12.11,38.1 10.15,36.14 v1(10.15,29.25)
  BOTTOM w0.15: P1.12 9.95,29.05 v1(10.15,29.25)
DIO_13: length 22.8
  TOP w0.15: v1(8.58,26.62) 10.54,26.62 11.52,27.61 11.52,29.3 10.88,29.95 10.88,36.44 12.16,37.73 U1.19
  BOTTOM w0.15: v1(8.58,26.62) 8.14,27.06 5.17,27.06 4.62,26.51 P1.15
DIO_14: length 22.7
  TOP w0.15: U1.20 12.08,37.23 11.17,36.32 11.17,30.08 11.82,29.43 11.82,27.48 10.16,25.83 v1(7.92,25.83)
  BOTTOM w0.15: v1(7.92,25.83) 5.21,25.83 4.62,25.24 P1.17
DIO_15: length 11.8
  TOP w0.15: v1(12.45,32.89) 12.45,34.76 14.42,36.73 U1.21
  BOTTOM w0.15: v1(12.45,32.89) 8.2,32.89 8.17,32.86 P1.6
DIO_16 / JTAG TDO: length 25.3
  TOP w0.15: U1.26 16.8,30.18 18.02,28.95 18.02,27.63 19.35,26.3 30.52,26.3 32.27,24.55 v1(33.12,24.55)
  BOTTOM w0.15: v1(33.12,24.55) 33.7,23.97 P2.19
DIO_17 / JTAG TDI: length 24.4
  TOP w0.15: v1(33,25.3) 31.95,25.3 30.65,26.6 19.48,26.6 18.32,27.76 18.32,29.08 17.2,30.2 17.2,31.74 17.3,31.84 U1.27
  BOTTOM w0.15: P2.17 33.7,25.24 33.64,25.3 v1(33,25.3)
DIO_18: length 17.3
  TOP w0.15: v1(17.67,31.54) 17.67,32.35 17.8,32.48 U1.28
  BOTTOM w0.15: P1.7 4.59,30.93 7.34,30.93 7.96,31.54 v1(17.67,31.54)
DIO_19: length 18.9
  TOP w0.15: U1.29 18.3,34.03 18.15,33.88 18.15,30.53 v1(17.89,30.26)
  BOTTOM w0.15: P1.9 4.52,29.73 7.8,29.73 8.34,30.26 v1(17.89,30.26)
DIO_20: length 34.5
  TOP w0.15: v1(38.33,30.9) 38.7,30.53 38.7,27 37.07,25.38 33.6,25.38 33.17,25.8 31.87,25.8 30.77,26.9 19.6,26.9 18.62,27.88 18.62,29.6 18.45,29.77 18.45,33.75 18.8,34.1 U1.30
  BOTTOM w0.15: v1(38.33,30.9) 38.33,31.3 38.04,31.59 P2.8
DIO_21: length 26.1
  TOP w0.15: v1(35.7,25.85) 33.55,25.85 33.3,26.1 32,26.1 30.9,27.2 19.73,27.2 18.92,28.01 18.92,29.73 18.75,29.9 18.75,33.56 19.3,34.11 U1.31
  BOTTOM w0.15: P2.18 36.31,25.24 v1(35.7,25.85)
DIO_22: length 18.5
  TOP w0.15: U1.32 19.8,34.04 19.46,33.7 v1(19.46,33.59)
  BOTTOM w0.15: P1.3 3.92,33.6 4.12,33.41 4.85,33.41 5.28,32.98 5.28,32.63 5.71,32.2 18.07,32.2 v1(19.46,33.59)
DIO_23: length 13.3
  TOP w0.15: v1(32.6,33.73) 32.34,33.99 31.75,33.99 31.36,34.38 21.95,34.38 U1.36
  BOTTOM w0.15: v1(32.6,33.73) 33.46,32.86 P2.5
DIO_24: length 16.8
  TOP w0.15: v1(32.02,34.46) 31.7,34.46 31.39,34.78 23.68,34.78 23.23,35.23 U1.37
  L3 w0.15: v1(35.73,30.9) 35.2,31.43 35.2,31.8 32.53,34.46 v1(32.02,34.46)
  BOTTOM w0.15: v1(35.73,30.9) 36.31,30.32 P2.10
DIO_25: length 19
  TOP w0.15: U1.38 23.15,35.73 23.8,35.08 31.51,35.08 31.65,34.94 v1(32.6,34.94)
  L3 w0.15: v1(35.75,29.62) 36.2,30.08 36.2,31.34 v1(32.6,34.94)
  BOTTOM w0.15: P2.11 34.98,29.62 v1(35.75,29.62)
DIO_26: length 16.4
  TOP w0.15: U1.39 23.23,36.23 24.03,35.43 v1(32.05,35.43)
  BOTTOM w0.15: P2.6 36.31,32.86 35.65,33.51 35.65,34.36 35.16,34.85 33.48,34.85 32.9,35.43 v1(32.05,35.43)
DIO_27: length 21.4
  TOP w0.15: v1(32.6,35.9) 23.98,35.9 23.15,36.73 U1.40
  L3 w0.15: v1(32.6,35.9) 36.5,32 36.5,29.28 v1(35.62,28.4)
  BOTTOM w0.15: v1(35.62,28.4) 35.01,27.78 P2.13
DIO_28: length 23.5
  TOP w0.15: v1(31.93,36.38) 31.83,36.28 24.07,36.28 23.12,37.23 U1.41
  L3 w0.15: v1(35.83,27.1) 36.8,28.08 36.8,32.37 32.8,36.38 v1(31.93,36.38)
  BOTTOM w0.15: v1(35.83,27.1) 36.42,26.5 37,26.5 P2.16
DIO_29: length 23.1
  TOP w0.15: U1.42 23.05,37.73 24.2,36.58 31.4,36.58 31.68,36.85 v1(32.6,36.85)
  L3 w0.15: v1(32.6,36.85) 32.74,36.85 37.48,32.12 37.48,29.05 v1(38.12,28.4)
  BOTTOM w0.15: P2.14 37.9,27.78 38.12,28 v1(38.12,28.4)
DIO_30: length 22.4
  TOP w0.15: v1(31.95,37.33) 31.73,37.33 31.28,36.88 24.38,36.88 23.03,38.23 U1.43
  L3 w0.15: v1(38.17,29.65) 37.77,30.05 37.77,32.35 32.8,37.33 v1(31.95,37.33)
  BOTTOM w0.15: P2.12 37.58,29.05 v1(38.17,29.65)
JTAG_TCK: length 43.8
  TOP w0.15: U1.25 16.3,30.25 17.72,28.83 17.72,27.51 19.23,26 30.4,26 32.33,24.08 36.2,24.08 39,26.88 39,33.33 38.33,34 v1(38.33,34.8)
  BOTTOM w0.15: P2.1 35.11,35.4 35.7,34.8 v1(38.33,34.8)
JTAG_TMS: length 42.6
  TOP w0.15: v1(38.86,34.14) 39.3,33.7 39.3,26.75 36.32,23.78 32.2,23.78 30.27,25.7 19.1,25.7 17.42,27.38 17.42,28.7 15.77,30.35 15.77,35.05 U1.24
  BOTTOM w0.15: P2.4 38.4,34.13 38.41,34.14 v1(38.86,34.14)
NRESET: length 20.3
  TOP w0.15: v1(31.99,33.33) 31.45,33.86 C351.1 25.19,33.85 R351.1 21.56,33.85 21.3,34.11 U1.35
  L3 w0.15: v1(33,26.58) 33.33,26.9 33.33,31.98 v1(31.99,33.33)
  BOTTOM w0.15: v1(33,26.58) 33.07,26.51 P2.15
RX_TX: length 15.4
  TOP w0.3: C32.1 23.73,46.43 L33.1 23.62,46.33 v1(23.62,45.53)
  TOP w0.32: C11.1 27.06,43.33 L12.1 26.48,42.76 v1(26.04,42.32) ; v1(18.62,42.3) 18.8,42.12 U1.7
  L3 w0.5: 22.04,42.32 22.01,42.29 22,42.3 v1(18.62,42.3) ; 22.04,42.32 v1(26.04,42.32) ; 22.04,42.32 23.62,43.9 v1(23.62,45.53)
N485531: length 8.3
  TOP w0.32: C36.1 23.66,52.97 24.25,53.56 24.25,55.05 22.45,56.85 J1.1
N485663: length 3.2
  TOP w0.3: 22.03,48.17 22.03,48.8 C34.1 22.8,48.83 C33.2
  TOP w0.32: C34.1 L34.1
N485675: length 1.6
  TOP w0.32: L34.2 C35.2 22.42,51.71 23.01,52.3
N485699: length 1.7
  TOP w0.32: C231.1 14.6,35.46 14.86,35.73 U1.23
N485705: length 8.2
  TOP w0.15: Y1.1 13.8,46.03 C81.1 14.15,46.1 18.3,41.95 U1.8
N485903: length 3.4
  TOP w0.3: L31.2 22.88,44.21 C31.1 22.88,45.67 L32.1 22.87,46.35 L33.2 22.8,46.43 C33.1
N501936: length 6.3
  TOP w0.15: C471.1 27.73,41.15 Y2.1 27.21,41.12 25.96,41.12 25.08,40.23 U1.47
N501950: length 6
  TOP w0.15: U1.46 25.65,39.73 26.1,39.28 27,39.28 Y2.3 27.04,39.24 C461.1
N510840: length 5.8
  TOP w0.3: L11.1 24.4,41.92 22.1,41.92 21.8,41.62 U1.1
  TOP w0.32: C12.1 26.39,43.95 25.84,43.41 25.84,43.36 L11.1
N510850: length 6.1
  TOP w0.3: U1.2 21.3,41.97 21.83,42.5 23.68,42.5 24.68,43.5
  TOP w0.32: L21.1 25.27,43.99 C21.1 24.75,43.5 24.68,43.5
N512042: length 1.6
  TOP w0.32: L14.1 29.11,47.31 C13.1 28,46.2 L13.2
N512564: length 10.7
  TOP w0.32: J2.1 32.53,56.93 30.29,54.69 C15.2
N514814: length 2.1
  TOP w0.32: C12.2 27.4,45.03 27.4,45.48 L13.1 27.31,45.58 26.85,45.58 26.48,45.2
N516767: length 3.5
  TOP w0.3: 21.59,43.98 21.96,44.36 C31.2 21.96,45.67 L32.2 21.95,46.35 C41.2 22.03,46.43 L42.1
N517777: length 4.9
  TOP w0.32: L61.1 17.84,45.74 17.84,44.98 17.85,44.96 L51.2 19.3,42.78 U1.6
N517785: length 4.7
  TOP w0.32: U1.5 19.8,43.2 L51.1 18.78,44.97 L52.2 18.78,45.73 C53.1
N517815: length 2.7
  TOP w0.32: C54.1 17.85,46.93 L61.2 ; C54.1 17.77,47.98 L53.1 ; C54.1 18.8,46.95 C53.2
N517942: length 1.6
  TOP w0.32: L53.2 17.08,48.63 C55.1 16.51,49.18 L54.1
N518069: length 1.6
  TOP w0.32: C57.1 14.78,50.94 C56.1 15.33,50.39 L54.2
N520038: length 8.6
  TOP w0.32: J3.1 12.35,53.38 C57.2
N520167: length 2.2
  TOP w0.3: U1.4 20.3,42.7 L41.1
N553230: length 1.9
  TOP w0.32: 29.77,47.96 30.28,48.48 C14.1 30.28,49.59 C15.1
N613500: length 2.4
  TOP w0.3: L31.1 20.8,42.13 U1.3
N621290: length 6.6
  TOP w0.15: U1.9 17.8,42 16.35,43.45 C91.1 13.8,43.53 Y1.2
N2095591: length 3.9
  TOP w0.5: R1.1 BAT+1.1
N2095595: length 39.3
  TOP w0.5: R1.2 v1(34.83,13.15) v1(34.83,13.9) R2.1
  L3 w0.7: v1(34.83,13.15) v1(34.83,13.9) v1(31.83,13.9) v1(8.92,13.9) v1(8.92,15)
  BOTTOM w0.7: v1(8.92,15) v1(8.92,13.9) BT1.1 ; BT1.2 v1(31.83,13.9)

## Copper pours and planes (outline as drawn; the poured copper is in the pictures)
GND on TOP: 0.45,66.55 0.45,0.5 40.37,0.5 40.37,66.55 ; 6 cut-outs
GND on BOTTOM: 0.5,0.45 0.43,0.48 0.4,0.55 0.4,66.5 0.43,66.57 0.5,66.6 40.32,66.6 40.39,66.57 40.42,66.5 40.42,0.55 40.39,0.48 40.32,0.45 ; 3 cut-outs
GND on L2: 0.45,66.55 0.45,0.5 40.37,0.5 40.37,66.55 ; 3 cut-outs
GND on L3: 0.4,0.45 0.4,66.6 40.42,66.6 40.42,0.45 ; 1 cut-out
VDD_EB on TOP: 31.33,31.9 33,31.9 33.17,31.73 33.17,30.33 32.95,30.1 31.33,30.1 31.12,30.3 31.12,31.7
VDD_EB on BOTTOM: 32.17,31.9 35.12,31.9 35.37,31.65 35.37,30.25 35.12,30 32.25,30 32,30.25 32,31.73
VDD_EB on BOTTOM: 32,30.75 32,30.28 31.2,29.48 31.2,21.98 34.3,18.88 34.3,16.9 34.4,16.8 35.25,16.8 35.35,16.9 35.35,19.28 32.08,22.54 32.1,29.03 33.52,30.45 33.52,30.75
VDDR on TOP: 20.72,30.7 21.5,30.7 21.5,29.58 22.8,29.58 22.8,29.03 20.72,29.03
VDDR on L3: 23.7,29.8 24.23,30.3 25.98,32.05 25.98,36.55 27.25,37.83 26.69,38.39 26.34,38.04 25.85,38.53 26.33,39 26.33,39.88 23.48,39.88 23.48,41.75 24.25,41.75 24.25,40.98 26.42,40.98 27.73,42.28 24.85,45.15 24.85,45.53 24.37,46 20.27,46 20.29,43.98 19.5,43.98 19.5,46.68 24.2,46.68 28.62,42.25 27.02,40.65 27,39.2 28.42,37.78 27.23,36.58 27.23,32.53 23.58,28.88 23.35,28.65 20.83,28.65 20.83,29.8
VDDS on TOP: 28.42,33.43 28.42,29.2 30.5,29.2 30.5,33.43
VDDS on L3: 31.1,26.12 17.2,26.1 15.72,27.68 15.72,33.55 15.3,34.05 12.83,34.05 12.83,34.7 13.15,34.95 15.3,34.95 15.72,35.65 15.72,39.3 13.6,39.3 13.6,40.43 16.52,40.43 16.52,28.23 17.17,27.62 19.58,27.62 19.58,34.38 24.1,34.38 24.1,37.73 25.05,37.73 25.05,31.98 24.1,31.98 24.1,32.9 20.67,32.9 20.67,28.53 23.26,28.53 24.95,30.2 28.42,30.2 28.42,33.4 31.1,33.4
N2095595 on BOTTOM: 31.55,14.4 35.52,14.4 35.73,14.23 35.7,12.7 35.52,12.53 30.58,12.53 30.58,13.43

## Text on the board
Ref Des/Silkscreen Top: Rev  :A0 | Model:CC1352P1F64EM-XD7793-XD24-PA24_10dBm | BAT - | 10dBm 2.4GHz | SUB1GHz | 2.4GHz | BAT +
XSECTION_CHART: *  SURFACE - AIR 0 MM | L1: TOP CONDUCTOR - COPPER 0.035 MM | *  DIELECTRIC - FR-4 0.175 MM | L2: L2 PLANE - COPPER 0.018 MM | *  DIELECTRIC - FR-4 1.14 MM | L3: L3 PLANE - COPPER 0.018 MM | L4: BOTTOM CONDUCTOR - COPPER 0.035 MM | DESIGN CROSS SECTION CHART | ___________________________ | TOTAL THICKNESS 1.60MM +/- 0.16MM
DIMENSION: FIGURE | FINISHED_SIZE | 0.2 | 1.501 | 3.0x1.0 | DRILL CHART: TOP to BOTTOM | ALL UNITS ARE IN MILLIMETERS | ROTATION | - | 90.000 | PLATED | NON-PLATED | QTY | 517 | 25 | 4 | 2
